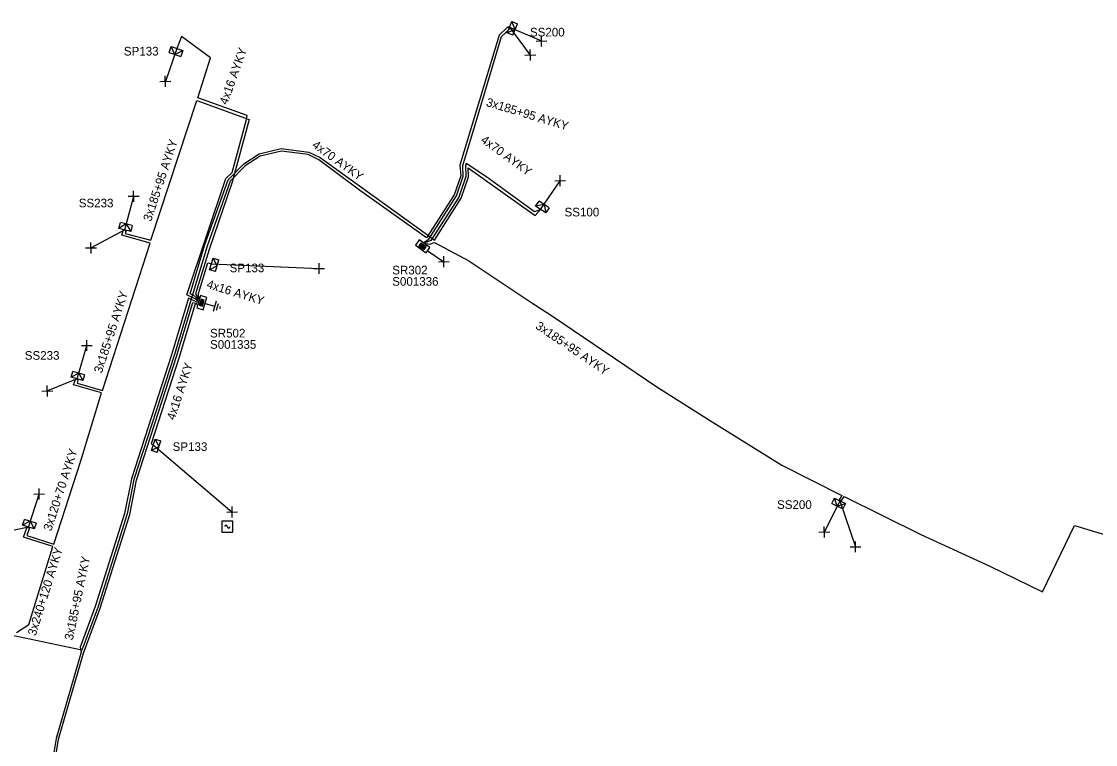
# Model space of a CAD drawing. Extents: x -762500 to -761285, y -1155006 to -1154135.
# Drawn here: x -762054.2 to -761930.7, y -1154533.7 to -1154450.6 of the extents above; entities that cross this region are included whole.
import ezdxf

# ---------------------------------------------------------------- set-up
doc = ezdxf.new("R2010")
doc.units = 0
for name, color, linetype in [('Vrstva 15', 7, 'Continuous'), ('Vrstva 28', 7, 'Continuous'), ('Vrstva 29', 7, 'Continuous'), ('Vrstva 30', 7, 'Continuous'), ('Vrstva 31', 7, 'Continuous'), ('Vrstva 33', 7, 'Continuous'), ('Vrstva 34', 7, 'Continuous'), ('Vrstva 5', 7, 'Continuous'), ('Vrstva 59', 7, 'Continuous'), ('Vrstva 6', 7, 'Continuous')]:
    doc.layers.add(name, color=color, linetype=linetype)

msp = doc.modelspace()

# ---------------------------------------------------------------- linework, layer by layer
at = {"layer": 'Vrstva 15'}
for points in [[(-762033.233, -1154482.992), (-762032.031, -1154483.337)], [(-762031.859, -1154482.736), (-762032.204, -1154483.937)], [(-762031.628, -1154483.053), (-762031.845, -1154483.81)], [(-762031.394, -1154483.381), (-762031.431, -1154483.509)], [(-762031.431, -1154483.509), (-762031.466, -1154483.632)]]:
    msp.add_lwpolyline(points, dxfattribs=at)
at = {"layer": 'Vrstva 28'}
for points in [[(-762008.501, -1154475.708), (-762008.931, -1154476.323)], [(-762007.272, -1154476.569), (-762008.501, -1154475.708)], [(-762008.931, -1154476.323), (-762007.702, -1154477.183)], [(-762008.301, -1154476.072), (-762008.518, -1154476.381)], [(-762008.518, -1154476.381), (-762007.908, -1154476.808)], [(-762008.29, -1154476.138), (-762008.452, -1154476.37)], [(-762008.452, -1154476.37), (-762007.92, -1154476.742)], [(-762008.278, -1154476.203), (-762008.386, -1154476.358)], [(-762008.386, -1154476.358), (-762007.932, -1154476.677)], [(-762008.266, -1154476.269), (-762008.321, -1154476.347)], [(-762008.321, -1154476.347), (-762007.943, -1154476.611)], [(-762007.692, -1154476.499), (-762008.301, -1154476.072)], [(-762007.757, -1154476.51), (-762008.29, -1154476.138)], [(-762007.823, -1154476.522), (-762008.278, -1154476.203)], [(-762007.889, -1154476.533), (-762008.266, -1154476.269)], [(-762008.26, -1154476.332), (-762007.95, -1154476.548)], [(-762007.943, -1154476.611), (-762007.889, -1154476.533)], [(-762007.932, -1154476.677), (-762007.823, -1154476.522)], [(-762007.92, -1154476.742), (-762007.757, -1154476.51)], [(-762007.908, -1154476.808), (-762007.692, -1154476.499)], [(-762007.702, -1154477.183), (-762007.272, -1154476.569)], [(-762033.633, -1154482.1), (-762034.072, -1154483.535)], [(-762032.916, -1154482.319), (-762033.633, -1154482.1)], [(-762033.57, -1154482.521), (-762033.788, -1154483.232)], [(-762033.788, -1154483.232), (-762033.427, -1154483.343)], [(-762033.539, -1154482.58), (-762033.729, -1154483.201)], [(-762033.729, -1154483.201), (-762033.458, -1154483.284)], [(-762033.508, -1154482.639), (-762033.67, -1154483.17)], [(-762033.67, -1154483.17), (-762033.489, -1154483.225)], [(-762033.476, -1154482.698), (-762033.611, -1154483.138)], [(-762033.611, -1154483.138), (-762033.521, -1154483.166)], [(-762033.209, -1154482.631), (-762033.57, -1154482.521)], [(-762033.554, -1154483.112), (-762033.443, -1154482.751)], [(-762033.268, -1154482.662), (-762033.539, -1154482.58)], [(-762033.521, -1154483.166), (-762033.386, -1154482.725)], [(-762033.327, -1154482.694), (-762033.508, -1154482.639)], [(-762033.489, -1154483.225), (-762033.327, -1154482.694)], [(-762033.386, -1154482.725), (-762033.476, -1154482.698)], [(-762033.458, -1154483.284), (-762033.268, -1154482.662)], [(-762033.427, -1154483.343), (-762033.209, -1154482.631)], [(-762033.355, -1154483.754), (-762032.916, -1154482.319)], [(-762034.072, -1154483.535), (-762033.355, -1154483.754)]]:
    msp.add_lwpolyline(points, dxfattribs=at)
at = {"layer": 'Vrstva 31'}
for points in [[(-761997.72, -1154452.161), (-761998.364, -1154451.887), (-761997.817, -1154450.598), (-761997.173, -1154450.872)], [(-761997.446, -1154451.516), (-761997.817, -1154450.598)], [(-761997.72, -1154452.161), (-761997.173, -1154450.872)], [(-761997.446, -1154451.516), (-761998.364, -1154451.887)], [(-762037.243, -1154454.153), (-762037.015, -1154453.491), (-762035.691, -1154453.947), (-762035.919, -1154454.609)], [(-762036.581, -1154454.381), (-762037.015, -1154453.491)], [(-762037.243, -1154454.153), (-762035.919, -1154454.609)], [(-762036.581, -1154454.381), (-762035.691, -1154453.947)], [(-761993.546, -1154472.023), (-761993.937, -1154472.603), (-761995.098, -1154471.82), (-761994.706, -1154471.24)], [(-761994.126, -1154471.631), (-761995.098, -1154471.82)], [(-761993.546, -1154472.023), (-761994.706, -1154471.24)], [(-761994.126, -1154471.631), (-761993.937, -1154472.603)], [(-762041.499, -1154474.05), (-762041.668, -1154474.73), (-762043.026, -1154474.391), (-762042.857, -1154473.712)], [(-762042.178, -1154473.881), (-762043.026, -1154474.391)], [(-762041.499, -1154474.05), (-762042.857, -1154473.712)], [(-762042.178, -1154473.881), (-762041.668, -1154474.73)], [(-762031.936, -1154479.356), (-762032.605, -1154479.152), (-762032.196, -1154477.813), (-762031.526, -1154478.018)], [(-762031.731, -1154478.687), (-762032.196, -1154477.813)], [(-762031.936, -1154479.356), (-762031.526, -1154478.018)], [(-762031.731, -1154478.687), (-762032.605, -1154479.152)], [(-762046.981, -1154491.21), (-762047.174, -1154491.883), (-762048.52, -1154491.497), (-762048.327, -1154490.824)], [(-762046.981, -1154491.21), (-762048.327, -1154490.824)], [(-762047.654, -1154491.017), (-762048.52, -1154491.497)], [(-762047.654, -1154491.017), (-762047.174, -1154491.883)], [(-762038.616, -1154500.147), (-762039.285, -1154499.943), (-762038.876, -1154498.604), (-762038.206, -1154498.809)], [(-762038.411, -1154499.478), (-762039.285, -1154499.943)], [(-762038.411, -1154499.478), (-762038.876, -1154498.604)], [(-762038.616, -1154500.147), (-762038.206, -1154498.809)], [(-761961.029, -1154506.031), (-761960.722, -1154505.402), (-761959.463, -1154506.016), (-761959.77, -1154506.645)], [(-761960.399, -1154506.338), (-761960.722, -1154505.402)], [(-761961.029, -1154506.031), (-761959.77, -1154506.645)], [(-761960.399, -1154506.338), (-761959.463, -1154506.016)], [(-762052.565, -1154508.281), (-762052.782, -1154508.947), (-762054.113, -1154508.515), (-762053.897, -1154507.849)], [(-762053.231, -1154508.065), (-762054.113, -1154508.515)], [(-762052.565, -1154508.281), (-762053.897, -1154507.849)], [(-762053.231, -1154508.065), (-762052.782, -1154508.947)]]:
    msp.add_lwpolyline(points, dxfattribs=at)
at = {"layer": 'Vrstva 34'}
for points in [[(-761994.409, -1154453.465), (-761994.431, -1154452.215)], [(-761995.045, -1154452.851), (-761993.795, -1154452.829)], [(-761996.335, -1154454.471), (-761995.085, -1154454.449)], [(-761995.699, -1154455.085), (-761995.721, -1154453.835)], [(-762038.315, -1154457.491), (-762037.065, -1154457.469)], [(-762037.679, -1154458.105), (-762037.701, -1154456.855)], [(-761992.259, -1154469.525), (-761992.281, -1154468.275)], [(-761992.895, -1154468.911), (-761991.645, -1154468.889)], [(-762041.955, -1154470.701), (-762040.705, -1154470.679)], [(-762041.319, -1154471.315), (-762041.341, -1154470.065)], [(-762046.229, -1154477.255), (-762046.251, -1154476.005)], [(-762046.865, -1154476.641), (-762045.615, -1154476.619)], [(-762019.989, -1154479.625), (-762020.011, -1154478.375)], [(-762006.275, -1154478.231), (-762005.025, -1154478.209)], [(-762005.639, -1154478.845), (-762005.661, -1154477.595)], [(-762020.625, -1154479.011), (-762019.375, -1154478.989)], [(-762047.345, -1154487.861), (-762046.095, -1154487.839)], [(-762046.709, -1154488.475), (-762046.731, -1154487.225)], [(-762051.885, -1154493.091), (-762050.635, -1154493.069)], [(-762051.249, -1154493.705), (-762051.271, -1154492.455)], [(-762052.199, -1154505.555), (-762052.221, -1154504.305)], [(-762052.835, -1154504.941), (-762051.585, -1154504.919)], [(-762029.989, -1154507.625), (-762030.011, -1154506.375)], [(-762029.936, -1154508.056), (-762031.186, -1154508.056)], [(-762031.186, -1154508.056), (-762031.186, -1154509.306)], [(-762030.625, -1154507.011), (-762029.375, -1154506.989)], [(-762029.936, -1154509.306), (-762029.936, -1154508.056)], [(-762031.186, -1154509.306), (-762029.936, -1154509.306)], [(-762030.561, -1154508.681), (-762030.562, -1154508.665), (-762030.564, -1154508.649), (-762030.568, -1154508.634), (-762030.574, -1154508.619), (-762030.581, -1154508.605), (-762030.59, -1154508.591), (-762030.6, -1154508.579), (-762030.611, -1154508.567), (-762030.623, -1154508.557), (-762030.637, -1154508.549), (-762030.651, -1154508.541), (-762030.666, -1154508.535), (-762030.681, -1154508.531), (-762030.697, -1154508.529), (-762030.713, -1154508.528), (-762030.729, -1154508.529), (-762030.745, -1154508.531), (-762030.76, -1154508.535), (-762030.775, -1154508.541), (-762030.789, -1154508.548), (-762030.803, -1154508.556), (-762030.815, -1154508.567), (-762030.826, -1154508.578), (-762030.836, -1154508.59), (-762030.845, -1154508.603), (-762030.853, -1154508.618), (-762030.858, -1154508.632), (-762030.863, -1154508.648), (-762030.865, -1154508.664), (-762030.866, -1154508.68), (-762030.866, -1154508.681)], [(-762030.561, -1154508.681), (-762030.56, -1154508.697), (-762030.558, -1154508.712), (-762030.554, -1154508.728), (-762030.549, -1154508.742), (-762030.542, -1154508.757), (-762030.534, -1154508.77), (-762030.524, -1154508.782), (-762030.513, -1154508.794), (-762030.502, -1154508.804), (-762030.488, -1154508.813), (-762030.475, -1154508.82), (-762030.46, -1154508.826), (-762030.445, -1154508.83), (-762030.429, -1154508.833), (-762030.414, -1154508.834), (-762030.398, -1154508.834), (-762030.382, -1154508.831), (-762030.367, -1154508.828), (-762030.352, -1154508.822), (-762030.338, -1154508.815), (-762030.325, -1154508.807), (-762030.313, -1154508.798), (-762030.301, -1154508.787), (-762030.291, -1154508.775), (-762030.282, -1154508.762), (-762030.275, -1154508.748), (-762030.269, -1154508.733), (-762030.265, -1154508.718), (-762030.262, -1154508.703), (-762030.261, -1154508.687), (-762030.261, -1154508.686)], [(-761962.505, -1154509.301), (-761961.255, -1154509.279)], [(-761961.869, -1154509.915), (-761961.891, -1154508.665)], [(-761958.289, -1154511.625), (-761958.311, -1154510.375)], [(-761958.925, -1154511.011), (-761957.675, -1154510.989)]]:
    msp.add_lwpolyline(points, dxfattribs=at)
at = {"layer": 'Vrstva 5'}
for points in [[(-762007.92, -1154475.96), (-762007.39, -1154475.63), (-762004.2, -1154470.66), (-762003.42, -1154468.38), (-762003.48, -1154467.15), (-762001.84, -1154461.73), (-761999.03, -1154452.34), (-761998.15, -1154451.5), (-761998.09, -1154451.24), (-761998.33, -1154451.26), (-761999.29, -1154452.18), (-762003.8, -1154467.12), (-762003.72, -1154468.34), (-762004.47, -1154470.53), (-762007.64, -1154475.47), (-762015.37, -1154469.98), (-762020.03, -1154466.49), (-762021.26, -1154465.9), (-762024.34, -1154465.51), (-762026.79, -1154466.1), (-762028.49, -1154467.19), (-762030.22, -1154468.96), (-762032.89, -1154476.45), (-762036.68, -1154489.02), (-762041.31, -1154503.25), (-762042.08, -1154507.22), (-762045.47, -1154517.96), (-762047.3, -1154522.87), (-762055.32, -1154521.2)], [(-762033.97, -1154482.78), (-762034.11, -1154482.55), (-762035.21, -1154482.02), (-762030.74, -1154468.64), (-762030.02, -1154467.95), (-762028.41, -1154462.03), (-762028.28, -1154461.4), (-762033.96, -1154459.38), (-762032.49, -1154454.77), (-762035.82, -1154452.32), (-762036.35, -1154453.71)], [(-762047.85, -1154491.69), (-762047.76, -1154491.89), (-762047.85, -1154492.17), (-762044.93, -1154493.04), (-762039.42, -1154476.08), (-762042.7, -1154475.16), (-762042.53, -1154474.64), (-762042.35, -1154474.56), (-762042.25, -1154474.74), (-762042.31, -1154474.96), (-762039.35, -1154475.76), (-762034.05, -1154459.68), (-762028.04, -1154461.85), (-762030.02, -1154469.09), (-762032.66, -1154476.8), (-762034.21, -1154481.9), (-762033.88, -1154482.47), (-762033.89, -1154482.53)], [(-762033.93, -1154482.66), (-762034.1, -1154482.38), (-762034.44, -1154482.07), (-762034.84, -1154481.9), (-762033.18, -1154476.36), (-762030.48, -1154468.8), (-762028.68, -1154466.96), (-762026.91, -1154465.82), (-762024.36, -1154465.21), (-762021.17, -1154465.61), (-762019.87, -1154466.23), (-762007.82, -1154474.95), (-762006.74, -1154475.74), (-762003.66, -1154470.92), (-762002.82, -1154468.47), (-762002.87, -1154467.43), (-761995.15, -1154472.91), (-761994.52, -1154472.21), (-761995.23, -1154472.49), (-762000.71, -1154468.5), (-762003.09, -1154466.92), (-762003.18, -1154467.18), (-762003.12, -1154468.42), (-762003.93, -1154470.79), (-762007.14, -1154475.79), (-762007.81, -1154476.03)], [(-762007.71, -1154476.11), (-762007.25, -1154476.2), (-762006.72, -1154476.02), (-762002.79, -1154478.1), (-761995.78, -1154482.81), (-761993.17, -1154484.48), (-761981.15, -1154492.59), (-761975.11, -1154496.45), (-761966.77, -1154501.61), (-761959.89, -1154505.09), (-761960.15, -1154505.52), (-761960.09, -1154505.71)], [(-762033.85, -1154482.41), (-762033.89, -1154481.86), (-762032.8, -1154478.33), (-762032.4, -1154478.48)], [(-762034.01, -1154482.9), (-762035.02, -1154482.4), (-762036.97, -1154488.93), (-762041.6, -1154503.18), (-762042.37, -1154507.15), (-762045.75, -1154517.86), (-762047.49, -1154522.53), (-762047.39, -1154523.12), (-762050.26, -1154533.05), (-762050.9, -1154536.96), (-762050.54, -1154540.43), (-762047.05, -1154546.25), (-762044.16, -1154549.07), (-762039.15, -1154552.42), (-762037.43, -1154553.09), (-762036.93, -1154553.25), (-762033.65, -1154554.46), (-762007.36, -1154559.35), (-761980.62, -1154564.29), (-761973.55, -1154565.6), (-761975.57, -1154574.58)], [(-762050.6, -1154536.97), (-762049.97, -1154533.11), (-762047.11, -1154523.22), (-762045.19, -1154518.06), (-762041.79, -1154507.29), (-762041.02, -1154503.33), (-762036.39, -1154489.11), (-762034.52, -1154482.89), (-762034.05, -1154483.03)], [(-762034.09, -1154483.15), (-762034.3, -1154483.19), (-762036.11, -1154489.2), (-762039.34, -1154499.17), (-762039.08, -1154499.27)], [(-762053.45, -1154508.73), (-762053.37, -1154508.95), (-762053.62, -1154509.7), (-762050.53, -1154510.68), (-762047.42, -1154501.12), (-762045.02, -1154493.31), (-762048.24, -1154492.37), (-762048.04, -1154491.75), (-762047.85, -1154491.69)], [(-761960.09, -1154505.71), (-761959.91, -1154505.69), (-761959.62, -1154505.22), (-761950.8, -1154509.6), (-761942.84, -1154513.23), (-761936.78, -1154516.16), (-761933.1, -1154508.56), (-761922.02, -1154511.87), (-761916.39, -1154514.1), (-761906, -1154516.65), (-761905.22, -1154513.26)], [(-762054.8, -1154520.84), (-762053.41, -1154519.94), (-762050.62, -1154510.96), (-762053.99, -1154509.9), (-762053.64, -1154508.83), (-762053.45, -1154508.73)]]:
    msp.add_lwpolyline(points, dxfattribs=at)
at = {"layer": 'Vrstva 59'}
for points in [[(-761998.09, -1154451.24), (-761994.42, -1154452.84)], [(-761998.09, -1154451.24), (-761995.71, -1154454.46)], [(-762036.35, -1154453.71), (-762037.69, -1154457.48)], [(-761994.52, -1154472.21), (-761992.27, -1154468.9)], [(-762042.35, -1154474.56), (-762041.33, -1154470.69)], [(-762042.35, -1154474.56), (-762046.24, -1154476.63)], [(-762007.44, -1154477.01), (-762005.65, -1154478.22)], [(-762032.4, -1154478.48), (-762020, -1154479)], [(-762047.85, -1154491.69), (-762046.72, -1154487.85)], [(-762047.85, -1154491.69), (-762051.26, -1154493.08)], [(-762039.08, -1154499.27), (-762030, -1154507)], [(-762053.45, -1154508.73), (-762052.21, -1154504.93)], [(-761960.09, -1154505.71), (-761961.88, -1154509.29)], [(-761960.09, -1154505.71), (-761958.3, -1154511)], [(-762053.45, -1154508.73), (-762057.08, -1154509.52)]]:
    msp.add_lwpolyline(points, dxfattribs=at)

# ---------------------------------------------------------------- texts
at = {"layer": 'Vrstva 29'}
for s, p in [('S001336', (-762011.59, -1154480.98)), ('S001335', (-762032.55, -1154488.23))]:
    msp.add_text(s, height=0.9943, dxfattribs=at).set_placement(p)
at = {"layer": 'Vrstva 30'}
for s, p in [('SR302', (-762011.59, -1154479.68)), ('SR502', (-762032.55, -1154486.93))]:
    msp.add_text(s, height=0.9943, dxfattribs=at).set_placement(p)
at = {"layer": 'Vrstva 33'}
for s, p in [('SS200', (-761995.75, -1154452.32)), ('SP133', (-762042.46, -1154454.51)), ('SS233', (-762047.65, -1154471.97)), ('SS100', (-761991.77, -1154473.01)), ('SP133', (-762030.3, -1154479.43)), ('SS233', (-762053.86, -1154489.49)), ('SP133', (-762036.85, -1154499.98)), ('SS200', (-761967.33, -1154506.64))]:
    msp.add_text(s, height=0.9943, dxfattribs=at).set_placement(p)
at = {"layer": 'Vrstva 6'}
for s, height, rotation, p in [('4x16 AYKY', 0.9943, 70.37751, (-762030.57, -1154460.24)), ('3x185+95 AYKY', 0.99429, 343.15717, (-762000.87, -1154460.29)), ('3x185+95 AYKY', 0.99429, 71.76184, (-762039.33, -1154473.66)), ('4x70 AYKY', 0.9943, 324.13094, (-762020.89, -1154464.99)), ('4x70 AYKY', 0.9943, 323.98381, (-762001.5, -1154464.41)), ('4x16 AYKY', 0.9943, 342.91098, (-762033.01, -1154481.21)), ('3x185+95 AYKY', 0.99429, 72.00302, (-762045, -1154491.11)), ('3x185+95 AYKY', 0.99429, 325.98998, (-761995.2, -1154485.84)), ('4x16 AYKY', 0.9943, 72.0421, (-762036.62, -1154496.49)), ('3x120+70 AYKY', 0.99428, 72.01006, (-762050.81, -1154509.25)), ('3x240+120 AYKY', 0.99429, 72.76377, (-762052.6, -1154521.3)), ('3x185+95 AYKY', 0.99429, 78.22658, (-762048.34, -1154521.8))]:
    msp.add_text(s, height=height, rotation=rotation, dxfattribs=at).set_placement(p)

doc.saveas('drawing.dxf')
